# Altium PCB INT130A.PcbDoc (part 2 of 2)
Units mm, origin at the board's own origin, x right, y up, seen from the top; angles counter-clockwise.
Board outline 103.68 x 57.35 mm, 2 copper layers (Top Layer, Bottom Layer), stack 1.575 mm thick; 110 components, 45 nets, 213 pads, 183 vias.
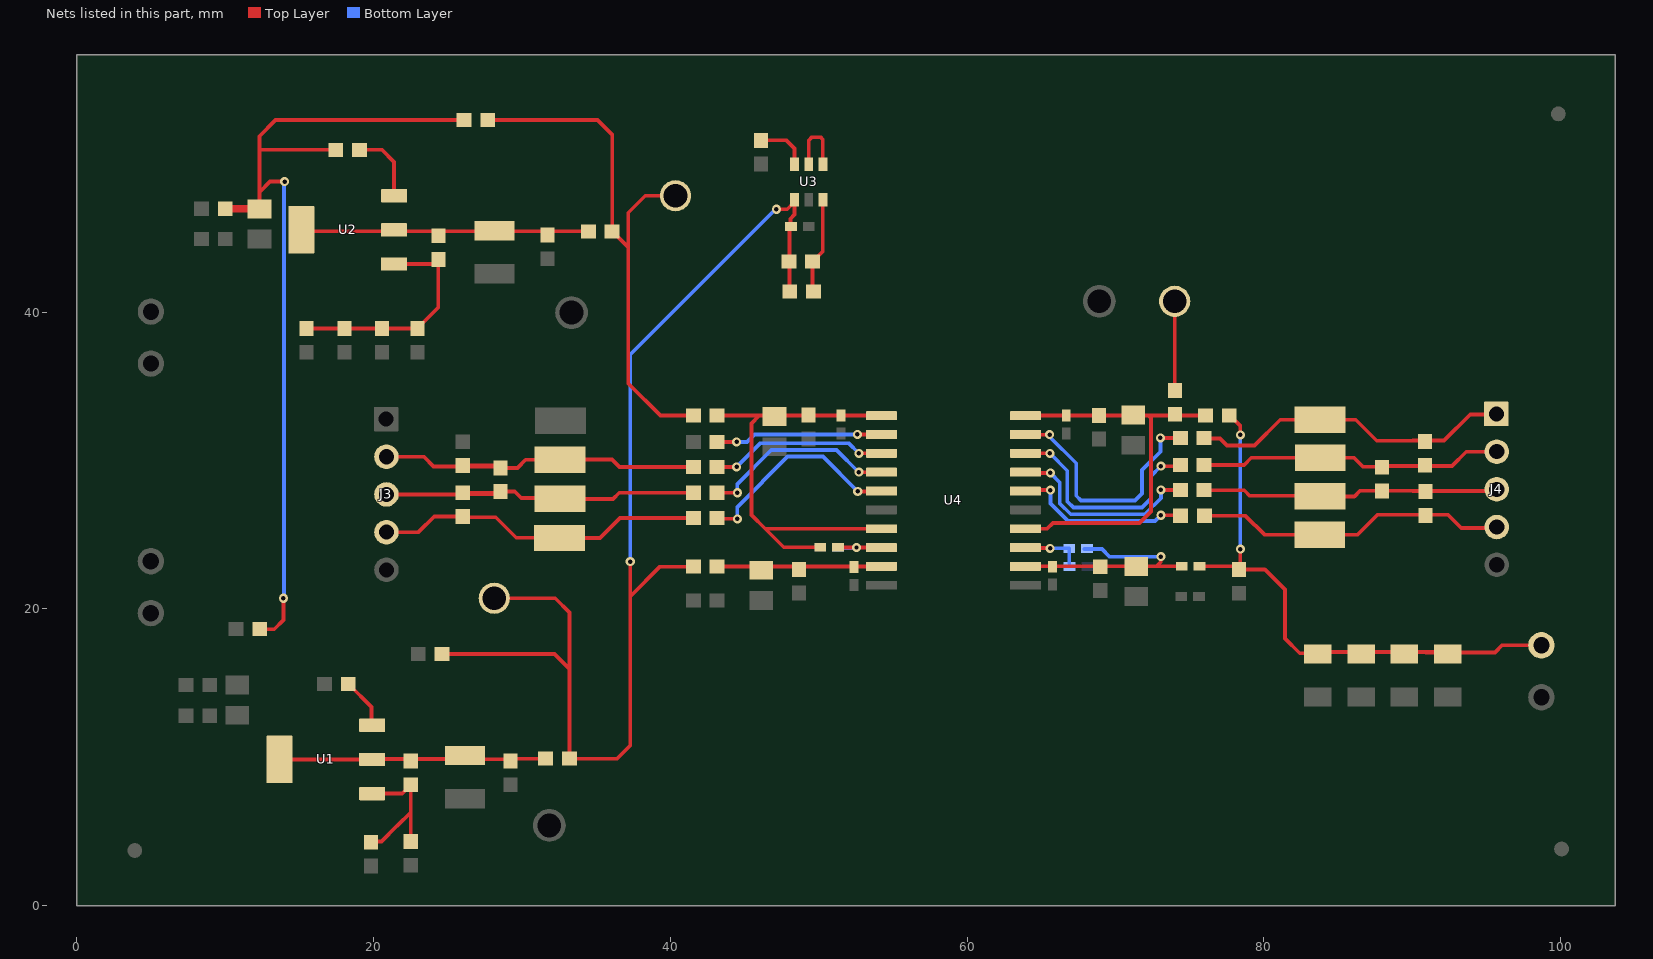
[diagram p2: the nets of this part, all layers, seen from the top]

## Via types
v1: diameter 0.61, hole 0.305, Top Layer to Bottom Layer, tented both sides, 182 vias
v2: diameter 0.6, hole 0.254, Top Layer to Bottom Layer, tented both sides, 1 vias

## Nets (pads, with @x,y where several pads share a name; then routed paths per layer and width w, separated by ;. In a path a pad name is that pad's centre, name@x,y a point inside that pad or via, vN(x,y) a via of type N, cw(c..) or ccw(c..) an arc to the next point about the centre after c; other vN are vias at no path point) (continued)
NetC2_1: C2.1 L3.2 R1.2 R4.1 R15.1 | length 60
  Top Layer w0.254: C2.1@11.828,46.956 C2.1@11.993,46.956 ; C2.1@11.94,47.04 12.315,47.415 12.315,48.076 ; C2.1@12.012,46.966 12.012,46.975 C2.1@12.315,46.975 ; R1.2@12.418,18.635 13.311,18.635 13.936,19.26 v1(13.936,20.719) ; v1(14.014,48.79) 13.03,48.79 12.315,48.076 ; R4.1@17.464,50.933 12.315,50.933 ; R15.1@26.1,52.94 13.409,52.94 12.315,51.846 12.315,50.933 ; 12.315,48.076 12.315,50.933
  Top Layer w0.508: L3.2@10.018,46.966 10.023,46.961 11.823,46.961 C2.1@11.828,46.956
  Bottom Layer w0.254: v1(13.936,20.719) 13.975,20.758 13.975,48.751 v1(14.014,48.79)
NetC3_1: C3.1 C5.1 R8.2 R17.1 U1.2 U1.4 | length 18
  Top Layer w0.254: U1.4@13.663,9.859 U1.2@19.913,9.859 19.95,9.896 22.515,9.896 26.985,9.896 27.022,9.934 27.089,9.867 C5.1@29.228,9.867 ; C5.1@29.228,9.753 29.386,9.912 31.318,9.912 R17.1@31.476,10.07
NetC4_1: C4.1 C6.1 R12.2 R18.1 U2.2 U2.4 | length 19.4
  Top Layer w0.254: U2.4@15.139,45.54 15.239,45.44 R18.1@34.482,45.44
NetJ3_2: J3.2 R13.1 R16.2 R20.1 TP4.1 | length 24.5
  Top Layer w0.254: J3.2@20.876,30.253 23.398,30.253 24.047,29.604 R16.2@28.458,29.604 ; R13.1@26.019,29.659 28.403,29.659 R16.2@28.458,29.604 ; R16.2@28.715,29.659 R16.2@28.66,29.604 ; R16.2@28.842,29.604 R16.2@28.66,29.604 ; R20.1@41.558,29.569 36.58,29.569 36.082,30.067 32.578,30.067 TP4.1@32.561,30.049 30.254,30.049 29.708,29.503 R16.2@28.559,29.503 ; R16.2@28.458,29.604 R16.2@28.66,29.604 ; R16.2@28.458,29.604 R16.2@28.559,29.503 ; R16.2@28.559,29.503 R16.2@28.66,29.604
NetJ3_3: J3.3 R14.2 R16.1 R21.1 TP5.1 | length 23.7
  Top Layer w0.254: J3.3@20.876,27.713 25.904,27.713 R14.2@26.019,27.828 28.484,27.828 R16.1@28.559,27.903 29.519,27.903 29.953,27.47 32.515,27.47 TP5.1@32.572,27.412 36.146,27.412 36.564,27.83 R21.1@41.558,27.83 ; R14.2@26.146,27.732 R16.1@28.675,27.732
NetJ3_4: J3.4 R14.1 R22.1 TP3.1 | length 22.4
  Top Layer w0.254: J3.4@20.876,25.173 23.04,25.173 24.095,26.228 R14.1@26.019,26.228 ; R14.1@26.146,26.173 28.242,26.173 29.623,24.792 32.529,24.792 TP3.1@32.539,24.782 35.272,24.782 36.619,26.129 R22.1@41.558,26.129 ; TP3.1@32.161,25.181 TP3.1@32.37,24.972
NetJ4_1: J4.1 R28.2 R38.2 TP12.1 | length 22.1
  Top Layer w0.254: R28.2@75.805,31.482 77.043,31.482 77.518,31.007 79.367,31.007 81.103,32.743 83.767,32.743 TP12.1@83.77,32.746 86.189,32.746 87.604,31.332 90.034,31.332 90.042,31.34 92.135,31.34 93.902,33.108 95.311,33.108 J4.1@95.566,32.852
NetJ4_2: J4.2 R29.2 R35.2 R38.1 TP14.1 | length 20.8
  Top Layer w0.254: R29.2@75.805,29.704 78.667,29.704 79.145,30.182 TP14.1@83.79,30.182 86.07,30.182 86.676,29.576 87.72,29.576 R35.2@87.734,29.562 ; R35.2@87.734,29.637 92.667,29.637 93.626,30.596 95.308,30.596 J4.2@95.592,30.312
NetJ4_3: J4.3 R30.2 R35.1 R37.2 TP13.1 | length 20.2
  Top Layer w0.254: R30.2@75.827,27.992 78.671,27.992 79.044,27.619 83.731,27.619 TP13.1@83.77,27.58 86.091,27.58 86.473,27.962 R35.1@87.734,27.962 ; R35.1@87.734,27.958 90.006,27.958 90.02,27.944 95.42,27.944 J4.3@95.592,27.772
NetJ4_4: J4.4 R31.2 R37.1 TP11.1 | length 21.3
  Top Layer w0.254: R31.2@75.831,26.271 78.764,26.271 80.029,25.006 TP11.1@83.76,25.006 86.316,25.006 87.654,26.344 92.403,26.344 93.296,25.45 95.374,25.45 J4.4@95.592,25.232
NetR2_2: R2.2 R5.2 R7.2 R10.2 R12.1 U2.1 | length 15.8
  Top Layer w0.254: R2.2@15.488,38.889 R5.2@18.059,38.889 R7.2@20.571,38.889 R10.2@22.958,38.889 22.958,38.914 24.373,40.329 R12.1@24.373,43.54 24.073,43.24 U2.1@21.389,43.24
NetR3_2: R3.2 U1.3 | length 3.5
  Top Layer w0.254: R3.2@18.307,14.931 18.332,14.931 19.873,13.39 19.873,12.159 U1.3@19.913,12.159
NetR4_2: R4.2 U2.3 | length 4.9
  Top Layer w0.254: R4.2@19.064,50.933 20.571,50.933 21.389,50.115 U2.3@21.389,47.84
NetR6_2: R6.2 R8.1 R9.2 U1.1 | length 10.5
  Top Layer w0.254: R6.2@19.833,4.275 19.897,4.338 20.54,4.338 21.608,5.406 21.63,5.406 22.515,6.291 ; U1.1@19.913,7.559 21.945,7.559 R8.1@22.515,8.128 ; R9.2@22.515,4.047 22.515,6.291 ; R8.1@22.515,8.153 R8.1@22.515,8.128 ; 22.515,6.291 R8.1@22.515,8.128
NetR19_2: R19.2 U4.2 | length 11.2
  Top Layer w0.254: R19.2@43.233,31.254 v1(44.47,31.254) ; v1(52.6,31.754) U4.2@54.229,31.754
  Bottom Layer w0.254: v1(44.47,31.254) 45.168,31.254 45.668,31.754 v1(52.6,31.754)
NetR20_2: R20.2 U4.3 | length 12
  Top Layer w0.254: R20.2@43.158,29.569 43.163,29.564 v1(44.47,29.564) ; v1(52.701,30.484) U4.3@54.229,30.484
  Bottom Layer w0.254: v1(44.47,29.564) 46.076,31.17 52.015,31.17 v1(52.701,30.484)
NetR21_2: R21.2 U4.4 | length 13.3
  Top Layer w0.254: R21.2@43.115,27.839 43.127,27.828 v1(44.519,27.828) ; v1(52.701,29.214) U4.4@54.229,29.214
  Bottom Layer w0.254: v1(44.519,27.828) 44.519,28.426 46.809,30.716 51.199,30.716 v1(52.701,29.214)
NetR22_2: R22.2 U4.5 | length 14.3
  Top Layer w0.254: R22.2@43.155,26.074 v1(44.519,26.074) ; v1(52.629,27.917) 54.203,27.917 U4.5@54.229,27.944
  Bottom Layer w0.254: v1(44.519,26.074) 44.519,26.873 47.907,30.261 50.285,30.261 v1(52.629,27.917)
NetR23_2: R23.2 U3.6 | length 3.5
  Top Layer w0.254: R23.2@46.121,51.572 47.831,51.572 48.377,51.026 U3.6@48.377,49.973
NetR24_1: R24.1 R25.1 U3.3 | length 6.5
  Top Layer w0.254: R25.1@49.648,41.375 49.59,41.433 R24.1@49.59,43.421 49.615,43.421 50.277,44.083 U3.3@50.277,47.573
NetR26_2: R26.2 R42.2 U4.8 | length 4.2
  Top Layer w0.254: R26.2@51.305,24.156 51.317,24.145 52.54,24.145 v2(52.552,24.134) U4.8@54.229,24.134
  Bottom Layer w0.254: R42.2@51.297,24.029 51.349,24.082 52.499,24.082 v2(52.552,24.134)
NetR27_2: R27.2 TP10.1 | length 6
  Top Layer w0.254: TP10.1@73.986,40.727 73.986,34.74 R27.2@74.01,34.716
NetR28_1: R28.1 U4.19 | length 16.7
  Top Layer w0.254: U4.19@63.929,31.754 63.945,31.738 v1(65.559,31.738) ; v1(73.021,31.522) 74.113,31.522 R28.1@74.154,31.482
  Bottom Layer w0.254: v1(65.559,31.738) 65.559,31.602 67.349,29.812 67.349,27.625 67.666,27.309 71.31,27.309 71.786,27.784 71.786,29.36 73.021,30.596 v1(73.021,31.522)
NetR29_1: R29.1 U4.18 | length 15.2
  Top Layer w0.254: U4.18@63.929,30.484 63.969,30.444 64.009,30.483 v1(65.575,30.483) ; v1(73.049,29.617) 74.108,29.617 R29.1@74.231,29.74
  Bottom Layer w0.254: v1(65.575,30.483) 66.745,29.313 66.745,27.247 67.165,26.827 71.786,26.827 72.389,27.431 72.389,28.957 v1(73.049,29.617)
NetR30_1: R30.1 U4.17 | length 13.4
  Top Layer w0.254: U4.17@63.929,29.214 63.983,29.16 v1(65.613,29.16) ; v1(73.056,28.019) R30.1@74.26,28.019
  Bottom Layer w0.254: v1(65.613,29.16) 66.245,28.528 66.245,27.105 66.977,26.373 71.974,26.373 73.056,27.456 v1(73.056,28.019)
NetR31_1: R31.1 U4.16 | length 11.8
  Top Layer w0.254: U4.16@63.978,27.992 63.993,28.008 v1(65.613,28.008) ; v1(73.056,26.313) R31.1@74.227,26.313
  Bottom Layer w0.254: v1(65.613,28.008) 65.613,27.095 66.789,25.919 72.663,25.919 v1(73.056,26.313)
NetR40_1: R40.1 R41.1 U4.13 | length 4.2
  Top Layer w0.254: U4.13@63.929,24.134 63.955,24.108 65.559,24.108 v1(65.585,24.082)
  Bottom Layer w0.254: v1(65.585,24.082) R40.1@66.88,24.082 66.88,22.894 R41.1@66.905,22.868
NetU3_4: U3.4 U3.5 | length 4.4
  Top Layer w0.254: U3.5@49.327,49.973 49.327,51.565 49.55,51.788 50.128,51.788 50.277,51.639 U3.4@50.277,49.973
VDD: C7.1 C10.1 C13.2 L6.2 U4.9 | length 11.1
  Top Layer w0.254: L6.2@43.158,22.849 43.172,22.864 46.125,22.864 48.665,22.864 52.39,22.864 U4.9@54.229,22.864
VDD_LOGIC: L5.1 R15.2 R18.2 TP8.1 | length 37.3
  Top Layer w0.254: R15.2@27.7,52.94 35.105,52.94 36.082,51.963 R18.2@36.082,45.44 36.107,45.44 37.157,44.39 ; TP8.1@40.353,47.84 38.316,47.84 37.171,46.695 37.171,35.196 39.343,33.024 L5.1@41.558,33.024
VDD_PWR: C9.1 L6.1 R11.2 R17.2 R24.2 R25.2 TP1.1 U3.1 | length 82.3
  Top Layer w0.254: R11.2@24.621,16.963 32.193,16.963 33.203,15.953 ; TP1.1@27.241,20.719 TP1.1@28.137,20.719 32.247,20.719 33.203,19.763 33.203,15.953 ; v1(37.301,23.19) 37.301,20.841 ; L6.1@41.558,22.849 39.31,22.849 37.301,20.841 ; v1(47.148,46.93) 47.884,46.93 U3.1@48.377,47.423 ; 48.027,41.882 48.027,43.914 48.027,45.668 C9.1@48.127,45.768 48.092,45.803 48.092,46.289 48.377,46.574 48.377,46.623 U3.1@48.377,47.423 ; U3.1@48.377,47.573 U3.1@48.377,47.423 ; 33.203,15.953 R17.2@33.203,9.912 36.425,9.912 37.301,10.787 37.301,20.841
  Bottom Layer w0.254: v1(37.301,23.19) 37.301,37.139 v1@47.14,46.978
VIO: C8.1 C11.1 C12.1 L5.2 R26.1 U4.1 U4.7 | length 31.4
  Top Layer w0.254: L5.2@43.158,33.024 45.997,33.024 ; R26.1@50.105,24.156 47.641,24.156 46.394,25.404 ; U4.7@54.229,25.404 46.394,25.404 ; U4.1@54.229,33.024 C12.1@51.49,33.024 49.304,33.024 47.013,33.024 45.997,33.024 ; 45.997,33.024 45.466,32.493 45.466,26.331 46.394,25.404
VISO_OUT: C20.1 J5.2 L9.2 R32.2 R33.2 R34.2 R36.2 R39.2 | length 40.1
  Top Layer w0.254: L9.2@75.66,22.873 78.104,22.873 C20.1@78.318,22.66 ; R32.2@77.659,33.041 77.684,33.041 78.409,32.316 v1(78.409,31.722) ; v1(78.409,24.035) 78.409,22.751 C20.1@78.318,22.66 ; R33.2@83.62,17.097 R33.2@83.636,17.097 ; 90.914,17.069 95.564,17.069 96.044,17.549 98.606,17.549 J5.2@98.779,17.722 ; R39.2@92.383,16.963 R39.2@92.438,17.017 ; R39.2@92.383,17.097 R33.2@83.636,17.097 ; C20.1@78.318,22.66 80.061,22.66 81.411,21.31 81.411,18.012 82.41,17.013 83.552,17.013 R33.2@83.636,17.097
  Bottom Layer w0.254: v1(78.409,24.035) v1(78.409,31.722)
VISOIN: C15.1 C16.1 C18.1 R27.1 R32.1 U4.14 U4.20 | length 27.4
  Top Layer w0.254: U4.14@63.929,25.404 65.39,25.404 65.782,25.796 71.623,25.796 72.389,26.561 72.389,32.846 72.211,33.024 ; U4.20@63.929,33.024 66.445,33.024 68.896,33.024 71.195,33.024 72.211,33.024 ; R32.1@75.859,33.024 74.01,33.024 72.211,33.024
VISOOUT: C14.1 C17.1 C19.1 L9.1 R40.2 U4.12 | length 16.7
  Top Layer w0.254: U4.12@63.929,22.864 63.934,22.868 65.632,22.868 68.972,22.868 C19.1@71.398,22.867 72.749,22.868 ; v1(73.049,23.519) 73.049,23.168 72.749,22.868 ; L9.1@74.46,22.873 74.455,22.868 72.749,22.868
  Bottom Layer w0.254: R40.2@67.914,24.035 69.08,24.035 69.596,23.519 v1(73.049,23.519)
pads on no net: FID1.1 FID2.1 FID3.1 H1.0 H2.0 H3.0 H4.0

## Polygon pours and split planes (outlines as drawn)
AGND1 on Bottom Layer "BBottom Layer-AGND1" (solid, remove dead copper, pour order 50): 55.376,2.789 53.412,0.817 5.854,0.817 0.61,6.42 0.61,53.47 3.756,56.615 52.777,56.604 55.376,54.005 55.376,39.342 53.662,37.628 41.221,37.628 39.311,35.719 39.311,15.637 41.243,13.706 53.593,13.706 55.376,12.247
GND1 on Bottom Layer "GND1Bottom" (solid, remove dead copper, pour order 45): 55.072,27.031 55.679,26.425 55.679,17.68 55.419,17.42 45.808,17.42 45.317,17.911 45.317,28.703 46.025,29.444 46.025,29.459 50.106,29.459 50.139,29.493 52.6,27.031
AGND2 on Bottom Layer "AGND2Bottom" (solid, remove dead copper, pour order 49): 65.871,34.024 65.846,33.999 65.846,26.564 71.305,26.564 71.621,26.88 71.621,33.728 71.916,34.024 78.993,34.024 79.043,34.074 80.55,32.566 81.05,32.566 81.05,18.267 78.547,15.763 65.673,15.763 64.722,15.763 62.894,13.935 62.894,2.709 64.919,0.684 97.534,1.028 102.488,5.981 102.488,52.161 98.039,56.61 65.547,56.61 62.641,53.704 62.479,53.866 62.894,54.281 62.864,35.864 64.704,34.024
AGND2 on Top Layer "Top Layer-AGND2" (solid, remove dead copper, pour order 52): 62.879,2.789 62.879,2.724 64.623,0.981 97.422,0.981 97.617,1.111 102.872,6.365 102.872,51.775 98.039,56.608 97.833,56.608 65.545,56.608 62.879,53.942 62.879,35.849 64.704,34.024 78.993,34.024 79.043,34.074 80.55,32.566 81.05,32.566 81.05,18.267 78.547,15.763 65.673,15.763 64.722,15.763 62.879,13.92
AGND1 on Top Layer "AGND1" (solid, remove dead copper, pour order 48): 52.777,56.604 55.376,54.005 55.376,39.342 53.753,37.719 41.312,37.719 39.311,35.719 39.311,15.637 41.243,13.706 53.6,13.706 55.376,12.253 55.376,2.789 53.412,0.825 5.854,0.817 1.04,5.993 1.04,53.908 3.747,56.615
AGND2 on Top Layer "AGND2Top" (solid, remove dead copper, pour order 54): 65.895,32.207 65.846,32.157 65.846,26.53 71.942,26.53 72.211,26.798 72.211,31.843 65.984,31.843 65.895,31.754
GND1 on Top Layer "GND1Top" (solid, remove dead copper, pour order 44): 54.229,25.729 45.719,25.729 45.719,31.957 54.229,31.957 54.229,27.568
GND1 on Top Layer "GND1Top2" (solid, remove dead copper, pour order 46): 55.65,18.908 55.305,19.264 53.865,19.264 52.94,20.188 52.94,21.699 45.109,21.699 45.109,21.594 45.317,21.386 45.317,17.911 45.808,17.42 55.419,17.42 55.65,17.651

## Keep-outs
Keep-Out Layer:
  the board outline again, w1.2
  text ".Layer_Name" at 3.459,-21.917 h1.52

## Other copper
Top Layer:
  text ".Layer_Name" at 3.459,-21.917 h1.52
Bottom Layer:
  pour cut-out: 53.865,19.264 52.94,20.188 52.945,26.996 55.638,26.996 55.638,19.264
  pour cut-out: 55.65,18.568
  text ".Layer_Name" at 3.459,-21.917 h1.52
Multi-Layer:
  pour cut-out: 10.094,13.205 10.094,8.86 3.773,8.86 3.747,8.834 1.333,11.249 1.333,28.504 5.303,28.504 10.094,23.713
  pour cut-out: 6.315,50.063 3.227,46.975 1.311,46.975 1.246,47.04 1.246,32.285 5.441,32.285 9.384,36.228 9.384,40.842 9.955,41.413 10.858,41.413 11.547,42.102 11.547,50.063
  pour cut-out: 78.393,18.647 76.843,17.097 64.413,17.097 64.413,24.291 64.508,24.386 77.234,24.386 78.393,23.227

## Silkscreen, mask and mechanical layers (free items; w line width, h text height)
Top Overlay:
  rectangle: 64.851,4.989 82.885,8.037
  text "INT130 Rev A" at 78.713,44.895 h1.52
  text "LDO1_IN" at 1.408,42.351 h1.14
  text "OUTA / OUTB / OUTC / IND / AGND2" at 93.921,35.636 h1.14
  text "5V" at 14.962,35.514 h0.6
  text "2.5V" at 19.477,35.514 h0.6
  text "1.8V" at 22.424,35.514 h0.6
  text "3.3V" at 16.632,35.449 h0.6
  text "L1GND" at 1.408,32.793 h1.14
  text "INA" at 13.97,32.092 h1.14
  text "INB" at 13.97,29.584 h1.14
  text "INC" at 13.97,27.153 h1.14
  text "LDO2_IN" at 1.408,25.459 h1.14
  text "OUTD" at 14.041,24.401 h1.14
  text "ANGD1" at 13.826,21.803 h1.14
  text "VISO_OUT" at 93.296,19.812 h1.14
  text "L2GND" at 1.403,16.02 h1.14
  text "AGND2" at 95.145,9.678 h1.14
  text "3.3V" at 23.963,3.687 h0.6
  text "5V" at 17.288,2.802 h0.6
  text ".Layer_Name" at 3.459,-21.917 h1.52
Bottom Overlay:
  text ".Layer_Name" at 3.459,-21.917 h1.52
Top Paste:
  text ".Layer_Name" at 3.459,-21.917 h1.52
Bottom Paste:
  text ".Layer_Name" at 3.459,-21.917 h1.52
Top Solder:
  text ".Layer_Name" at 3.459,-21.917 h1.52
  text ".Layer_Name" at 3.459,-21.917 h1.52
Bottom Solder:
  text ".Layer_Name" at 3.459,-21.917 h1.52
Drill Guide:
  text ".Layer_Name" at 3.459,-21.917 h1.52
M1 Board Outline:
  lines w0.178: 0.61,0.817 0.61,56.61 102.872,56.61 102.872,0.817 0.61,0.817
  text ".Layer_Name" at 3.459,-21.917 h1.52
M2 Board Dimensions:
  rectangle: -8.022,-10.272 1.503,-7.097
  rectangle: -11.197,-7.097 -8.022,-3.922
  lines w0.178: -11.197,-7.097 14.203,-7.097 ; -8.022,-10.272 -8.022,-3.922 ; -4.847,-10.272 -4.847,-3.922 ; 1.503,-10.272 1.503,-3.922 ; 7.853,-10.272 7.853,-3.922 ; -11.197,-10.272 -11.197,-3.922 14.203,-3.922 14.203,-10.272 -11.197,-10.272
M3 3D STEP Top:
  text ".Layer_Name" at 3.459,-21.917 h1.52
M4 3D STEP Bottom:
  text ".Layer_Name" at 3.459,-21.917 h1.52
M5 Assembly Top:
  lines w0.254: -18.613,-23.738 149.027,-23.738 ; -18.613,-18.573 149.077,-18.573 ; -18.613,-13.408 -18.613,-28.902 83.114,-28.902 149.077,-28.902 149.077,-13.408 -18.601,-13.408 -18.601,-28.902 21.417,-28.902 ; 43.998,-28.902 43.998,-13.408 ; 76.179,-18.573 76.179,-13.408 ; 97.515,-18.573 97.515,-13.408 ; 113.314,-29.068 113.314,-23.916
  text "COMPONENTS MARKED 'DNP' SHOULD NOT BE POPULATED." at 18.102,-8.201 h1.52
  text "ASSEMBLY VARIANT:" at 18.09,-11.135 h1.52
  text ".VariantName" at 44.404,-11.135 h1.52
  text "PCB VIEWED FROM TOP SIDE" at -17.001,-16.765 h1.52
  text "BOARD #:" at 45.903,-16.765 h1.52
  text "ISO6741DWEVM" at 59.758,-16.765 h1.52
  text "REV:" at 81.209,-16.765 h1.52
  text ".PCB_Rev" at 88.613,-16.765 h1.52
  text "SVN REV:" at 102.494,-16.765 h1.52
  text ".VersionControl_RevNumber" at 115.346,-16.765 h1.52
  text "PLOT NAME =" at -17.001,-27.146 h1.52
  text ".plot_File_Name" at 3.459,-27.146 h1.52
  text "GENERATED    :" at 45.953,-27.146 h1.52
  text ".Print_Date" at 68.039,-27.146 h1.52
  text ".Print_Time" at 86.555,-27.146 h1.52
  text "TEXAS INSTRUMENTS" at 118.674,-27.146 h1.52
M6 Assembly Bottom:
  lines w0.254: -18.626,-18.586 149.065,-18.586 ; -18.575,-23.75 149.065,-23.75 ; 17.137,-29.08 17.137,-23.928 ; 32.936,-18.586 32.936,-13.421 ; 54.272,-18.586 54.272,-13.421 ; 86.454,-28.915 86.454,-13.421 ; 109.034,-28.915 149.052,-28.915 149.052,-13.421 -18.626,-13.421 -18.626,-28.915 47.338,-28.915 149.065,-28.915 149.065,-13.421
  text "COMPONENTS MARKED 'DNP' SHOULD NOT BE POPULATED." at 143.794,-8.189 h1.52
  text ".VariantName" at 117.277,-11.135 h1.52
  text "ASSEMBLY VARIANT:" at 143.667,-11.135 h1.52
  text ".VersionControl_RevNumber" at 15.105,-16.778 h1.52
  text "SVN REV:" at 27.957,-16.778 h1.52
  text ".PCB_Rev" at 41.839,-16.778 h1.52
  text "REV:" at 49.243,-16.778 h1.52
  text "ISO6741DWEVM" at 70.693,-16.778 h1.52
  text "BOARD #:" at 84.549,-16.778 h1.52
  text "PCB VIEWED FROM BOTTOM SIDE" at 147.452,-16.778 h1.52
  text "TEXAS INSTRUMENTS" at 11.778,-27.158 h1.52
  text ".Print_Time" at 43.896,-27.158 h1.52
  text ".Print_Date" at 62.413,-27.158 h1.52
  text "GENERATED    :" at 84.498,-27.158 h1.52
  text ".plot_File_Name" at 126.992,-27.158 h1.52
  text "PLOT NAME =" at 147.452,-27.158 h1.52
M9 Title Sheet:
  drawing of 57 lines, arcs and shapes, not listed
  text "1" at 7.595,204.016 h1.52
  text "2" at 70.985,204.016 h1.52
  text "3" at 134.214,204.016 h1.52
  text "4" at 197.884,204.016 h1.52
  text "5" at 261.358,204.016 h1.52
  text "6" at 324.985,204.016 h1.52
  text "A" at -21.776,174.983 h1.52
  text "A" at 354.144,174.983 h1.52
  text "B" at -21.776,114.531 h1.52
  text "B" at 354.144,114.531 h1.52
  text "C" at -21.776,54.206 h1.52
  text "C" at 354.144,54.206 h1.52
  text "PROJECT TITLE:" at 276.928,6.937 h1.52
  text ".PRJ_Title" at 278.198,3.55 h1.52
  text "DESIGNED FOR:" at 276.928,-0.708 h1.52
  text ".PRJ_Customer" at 278.198,-4.264 h1.52
  text "D" at -21.776,-5.992 h1.52
  text "D" at 354.144,-5.992 h1.52
  text "FILE NAME:" at 276.928,-8.328 h1.52
  text ".PCB_File_Name_No_Path" at 278.198,-11.376 h1.52
  text "Texas Instruments (TI) and/or its licensors do not warrant the accuracy or completeness of this specification" at 150.703,-15.487 h1.14
  text "ENGINEER:" at 276.928,-15.694 h1.52
  text "LAYOUT BY:" at 315.155,-15.694 h1.52
  text "or any information contained therein. TI and/or its licensors do not warrant that this design will meet" at 149.56,-18.349 h1.14
  text ".PRJ_Engineer" at 278.198,-19.631 h1.52
  text ".PCB_Layout" at 316.438,-19.631 h1.52
  text "the specifications, will be suitable for your application or fit for any particular purpose, or will operate in" at 149.56,-21.211 h1.14
  text "ALTIUM DESIGNER VERSION:" at 315.155,-23.568 h1.52
  text "an implementation. TI and/or its licensors do not warrant that the design is production worthy. You should" at 149.56,-24.072 h1.14
  text "completely validate and test your design implementation to confirm the system functionality for your application." at 150.703,-26.934 h1.14
  text ".print_Scale" at 278.198,-26.955 h1.52
  text ".Application_BuildNumber" at 316.438,-26.955 h1.52
  text "1" at 7.595,-32.204 h1.52
  text "2" at 70.985,-32.204 h1.52
  text "3" at 134.214,-32.204 h1.52
  text "4" at 197.884,-32.204 h1.52
  text "5" at 261.358,-32.204 h1.52
  text "6" at 324.985,-32.204 h1.52
M10 Fab Notes:
  drawing of 185 lines, arcs and shapes, not listed
  text "DESIGN INFORMATION" at 303.281,150.002 h1.52
  text "MIN. TRACK WIDTH:" at 286.909,145.43 h1.52
  text "10" at 314.754,145.431 h1.52
  text "MIL" at 318.685,145.43 h1.52
  text "MIN. CLEARANCE:" at 286.909,142.078 h1.52
  text "0.2" at 313.23,142.078 h1.52
  text "mm" at 318.685,142.078 h1.52
  text "MIN. VIA PAD SIZE:" at 286.909,138.725 h1.52
  text "24" at 313.992,138.725 h1.52
  text "MIL" at 318.685,138.725 h1.52
  text "0.05mm (2MIL)" at 304.562,135.125 h1.52
  text "MINIMUM ANNULAR RING" at 278.547,135.017 h1.52
  text "EXTERNAL" at 322.546,135.017 h1.52
  text "PER" at 283.627,132.019 h1.52
  text "IPC-D-275 CLASS 2 LEVEL C" at 289.215,132.019 h1.52
  text "MIL, HOLES" at 327.016,129.167 h1.52
  text "+/-" at 317.048,129.149 h1.52
  text "+/-" at 338.739,129.149 h1.52
  text "REGISTRATION TOLERANCES:" at 278.547,129.022 h1.52
  text "METAL" at 309.021,129.022 h1.52
  text "5" at 323.657,129.022 h1.52
  text "3" at 344.815,129.022 h1.52
  text "MIL" at 347.768,129.022 h1.52
  text "MATERIAL:" at 276.648,123.702 h1.52
  text "FR-4 High Tg" at 301.703,120.137 h1.52
  text "FR-408" at 287.341,119.92 h1.52
  text "X" at 297.806,119.92 h1.52
  text "OTHER" at 325.136,119.92 h1.52
  text "62 MIL (1.6mm) +/-10%" at 295.472,115.787 h1.52
  text "THICKNESS:" at 278.547,115.678 h1.52
  text "X" at 292.216,115.678 h1.52
  text "OTHER" at 328.108,115.678 h1.52
  text "TOLERANCE:" at 278.547,111.665 h1.52
  text "X" at 299.865,111.665 h1.52
  text "ANSI IPC-6012 TYPE 3 CLASS 2" at 304.614,111.665 h1.52
  text "OTHER +/-" at 304.613,107.702 h1.52
  text "BOW & TWIST:" at 278.547,103.714 h1.52
  text "X" at 299.865,103.714 h1.52
  text "ANSI IPC-6012 TYPE 3 CLASS 2" at 304.614,103.714 h1.52
  text "OTHER +/-" at 304.613,99.688 h1.52
  text "DRILLING:" at 276.648,96.171 h1.52
  text "REFERENCE:" at 278.547,93.199 h1.52
  text "X" at 295.012,93.199 h1.52
  text "AS SHOWN" at 299.762,93.199 h1.52
  text "X" at 317.897,93.199 h1.52
  text "NC_DRILL FILES" at 321.377,93.199 h1.52
  text "PTH MIN COPPER THICKNESS:" at 278.547,89.186 h1.52
  text "X" at 312.843,89.186 h1.52
  text "1MIL" at 316.323,89.186 h1.52
  text "OTHER" at 328.946,89.186 h1.52
  text "BOARD FINISH:" at 276.648,85.147 h1.52
  text "SILKSCREEN:" at 280.59,82.15 h1.52
  text "X" at 304.689,82.15 h1.52
  text "TOP" at 307.89,82.15 h1.52
  text "BOTTOM" at 320.869,82.15 h1.52
  text "X" at 317.643,82.023 h1.52
  text "SILKSCREEN COLOR:" at 280.59,77.908 h1.52
  text "X" at 304.663,77.908 h1.52
  text "WHITE" at 307.89,77.908 h1.52
  text "OTHER" at 320.869,77.908 h1.52
  text "SOLDER RESIST COLOR:" at 280.59,73.59 h1.52
  text "X" at 295.011,69.546 h1.52
  text "GREEN" at 298.238,69.546 h1.52
  text "BLUE" at 313.249,69.546 h1.52
  text "OTHER" at 326.914,69.546 h1.52
  text "IMMERSION GOLD (ENIG)" at 303.597,64.758 h1.52
  text "ENEPIG" at 337.571,64.675 h1.52
  text "SURFACE FINISH:" at 276.648,64.649 h1.52
  text "X" at 298.849,64.649 h1.52
  text "IMM. TIN/SILVER OR EQUIV" at 285.018,60.661 h1.52
  text "OTHER" at 321.377,60.661 h1.52
  text "ARRAY/PANEL:" at 276.648,56.115 h1.52
  text "CUT AND TRIM PER MECH LAYER 1" at 303.597,56.006 h1.52
  text "N.C. ROUTE" at 303.597,52.152 h1.52
  text "X" at 320.844,52.152 h1.52
  text "V. SCORE" at 325.594,52.152 h1.52
  text "CERTIFICATION:" at 276.648,48.673 h1.52
  text "MATERIALS AND WORKMANSHIP FOR ALL PCBS" at 295.063,48.673 h1.52
  text "TO MEET OR EXCEED THE REQUIREMENTS OF:" at 295.063,46.183 h1.52
  text "X" at 285.576,42.716 h1.52
  text "ANSI IPC-A-600F CLASS ->" at 289.107,42.716 h1.52
  text "X" at 330.739,42.716 h1.52
  text "2" at 333.76,42.716 h1.52
  text "1" at 325.759,42.678 h1.52
  text "3" at 342.751,42.678 h1.52
  text "X" at 285.628,38.665 h1.52
  text "UL 94V-0" at 289.107,38.665 h1.52
  text "X" at 306.253,38.665 h1.52
  text "RoHS" at 309.731,38.665 h1.52
  text "OTHER" at 326.099,38.665 h1.52
  text "PER ORDER" at 336.184,38.665 h1.52
  text "ADDITIONAL REQUIREMENTS:" at 276.648,35.084 h1.52
  text "MICROSECTION:" at 278.547,32.163 h1.52
  text "YES" at 301.553,32.163 h1.52
  text "REQUIRED" at 323.435,28.197 h1.52
  text "BARE BOARD ELEC. TEST:" at 278.547,28.124 h1.52
  text "NONE" at 311.713,28.124 h1.52
  text "X" at 320.209,28.124 h1.52
  text "PER ORDER" at 338.471,28.124 h1.52
  text "MANUFACTURER'S UL:" at 278.547,24.136 h1.52
  text "RAIL" at 308.157,24.027 h1.52
  text "METAL" at 320.649,24.027 h1.52
  text "X" at 330.179,24.018 h1.52
  text "SILK" at 333.645,24.027 h1.52
M11 Gerber Information:
  lines w0.254: -18.613,-23.738 149.027,-23.738 ; -18.613,-18.573 149.077,-18.573 ; -18.613,-13.408 -18.613,-28.902 83.114,-28.902 149.077,-28.902 149.077,-13.408 -18.601,-13.408 -18.601,-28.902 21.417,-28.902 ; 43.998,-28.902 43.998,-13.408 ; 76.179,-18.573 76.179,-13.408 ; 97.515,-18.573 97.515,-13.408 ; 113.314,-29.068 113.314,-23.916
  text "ALL ARTWORK VIEWED FROM TOP SIDE" at -17.001,-16.765 h1.52
  text "BOARD #:" at 45.903,-16.765 h1.52
  text "ISO6741DWEVM" at 59.758,-16.765 h1.52
  text "REV:" at 81.209,-16.765 h1.52
  text ".PCB_Rev" at 88.613,-16.765 h1.52
  text "SVN REV:" at 102.494,-16.765 h1.52
  text ".VersionControl_RevNumber" at 115.346,-16.765 h1.52
  text "LAYER NAME =" at -17.001,-21.917 h1.52
  text "PLOT NAME =" at -17.001,-27.146 h1.52
  text ".plot_File_Name" at 3.459,-27.146 h1.52
  text "GENERATED    :" at 45.953,-27.146 h1.52
  text ".Print_Date" at 68.039,-27.146 h1.52
  text ".Print_Time" at 86.555,-27.146 h1.52
  text "TEXAS INSTRUMENTS" at 118.674,-27.146 h1.52
M12 Stackup:
  drawing of 165 lines, arcs and shapes, not listed
  text "Layer" at 238.488,191.404 h1.52
  text "Name" at 248.899,191.404 h1.52
  text "Material" at 270.737,191.404 h1.52
  text "Thickness" at 292.576,191.404 h1.52
  text "Constant" at 309.081,191.404 h1.52
  text "Board Layer Stack" at 323.556,191.404 h1.52
  text "Top Overlay" at 248.899,188.356 h1.52
  text "Top Solder" at 248.899,185.308 h1.52
  text "Solder Resist" at 270.737,185.308 h1.52
  text "0.40mil" at 292.576,185.308 h1.52
  text "3.5" at 309.081,185.308 h1.52
  text "1" at 238.488,182.26 h1.52
  text "Top Layer" at 248.899,182.26 h1.52
  text "Copper" at 270.737,182.26 h1.52
  text "1.40mil" at 292.576,182.26 h1.52
  text "Dielectric1" at 248.899,179.212 h1.52
  text "FR-4" at 270.737,179.212 h1.52
  text "59.20mil" at 292.576,179.212 h1.52
  text "4.8" at 309.081,179.212 h1.52
  text "2" at 238.488,176.164 h1.52
  text "Bottom Layer" at 248.899,176.164 h1.52
  text "Copper" at 270.737,176.164 h1.52
  text "1.40mil" at 292.576,176.164 h1.52
  text "Bottom Solder" at 248.899,173.116 h1.52
  text "Solder Resist" at 270.737,173.116 h1.52
  text "0.40mil" at 292.576,173.116 h1.52
  text "3.5" at 309.081,173.116 h1.52
M13 Component Bodies Top:
  text ".Layer_Name" at 3.459,-21.917 h1.52
M14 Component Bodies Bottom:
  text ".Layer_Name" at 3.459,-21.917 h1.52
M15 Courtyards Top:
  text ".Layer_Name" at 3.459,-21.917 h1.52
M16 Courtyards Bottom:
  text ".Layer_Name" at 3.459,-21.917 h1.52
Drill Drawing:
  circle w0.254: c146.261,36.016 r0.847
  lines w0.254: 145.414,38.979 147.108,38.979 147.108,40.672 145.414,40.672 145.414,38.979 ; 145.414,44.482 147.108,44.482 146.261,42.789 145.414,44.482 ; 145.414,47.022 145.838,47.022 146.261,46.599 146.684,47.022 147.108,47.022 146.684,47.446 147.108,47.869 146.684,47.869 146.261,48.292 145.838,47.869 145.414,47.869 145.838,47.446 145.414,47.022 ; 145.414,50.832 145.838,50.832 145.838,50.409 146.684,50.409 146.684,50.832 147.108,50.832 147.108,51.679 146.684,51.679 146.684,52.102 145.838,52.102 145.838,51.679 145.414,51.679 145.414,50.832 ; 145.414,54.219 145.414,54.642 145.838,55.066 145.414,55.489 145.414,55.912 145.838,55.912 146.261,55.489 146.684,55.912 147.108,55.912 147.108,55.489 146.684,55.066 147.108,54.642 147.108,54.219 146.684,54.219 146.261,54.642 145.838,54.219 145.414,54.219
  lines w0.305: 143.896,34.026 240.898,34.026 ; 143.896,56.886 240.898,56.886 ; 157.888,30.216 157.888,60.696 ; 174.089,30.216 174.089,60.696 ; 208.267,30.216 208.267,60.696 ; 221.117,30.216 221.117,60.696 ; 143.896,30.216 240.898,30.216 240.898,60.696 143.896,60.696 143.896,30.216
  text "Symbol" at 146.182,58.029 h1.83
  text "Quantity" at 159.031,58.029 h1.83
  text "Finished Hole Size" at 175.232,58.029 h1.83
  text "Plated" at 209.41,58.029 h1.83
  text "Hole Type" at 222.26,58.029 h1.83
  text "1" at 159.031,54.219 h1.52
  text "10.00mil (0.254mm)" at 175.232,54.219 h1.52
  text "PTH" at 209.41,54.219 h1.52
  text "Round" at 222.26,54.219 h1.52
  text "182" at 159.031,50.409 h1.52
  text "12.01mil (0.305mm)" at 175.232,50.409 h1.52
  text "PTH" at 209.41,50.409 h1.52
  text "Round" at 222.26,50.409 h1.52
  text "10" at 159.031,46.599 h1.52
  text "40.00mil (1.016mm)" at 175.232,46.599 h1.52
  text "PTH" at 209.41,46.599 h1.52
  text "Round" at 222.26,46.599 h1.52
  text "6" at 159.031,42.789 h1.52
  text "43.31mil (1.100mm)" at 175.232,42.789 h1.52
  text "PTH" at 209.41,42.789 h1.52
  text "Round" at 222.26,42.789 h1.52
  text "3" at 159.031,38.979 h1.52
  text "62.99mil (1.600mm)" at 175.232,38.979 h1.52
  text "PTH" at 209.41,38.979 h1.52
  text "Round" at 222.26,38.979 h1.52
  text "3" at 159.031,35.169 h1.52
  text "63.00mil (1.600mm)" at 175.232,35.169 h1.52
  text "PTH" at 209.41,35.169 h1.52
  text "Round" at 222.26,35.169 h1.52
  text "205 Total" at 159.031,31.359 h1.52
  text ".Layer_Name" at 3.459,-21.917 h1.52

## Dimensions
102.872,0.817 to 102.872,56.61 on M2 Board Dimensions
0.61,0.817 to 102.872,56.61 on M2 Board Dimensions
-11.197,-10.272 to 14.203,-10.272 on M2 Board Dimensions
